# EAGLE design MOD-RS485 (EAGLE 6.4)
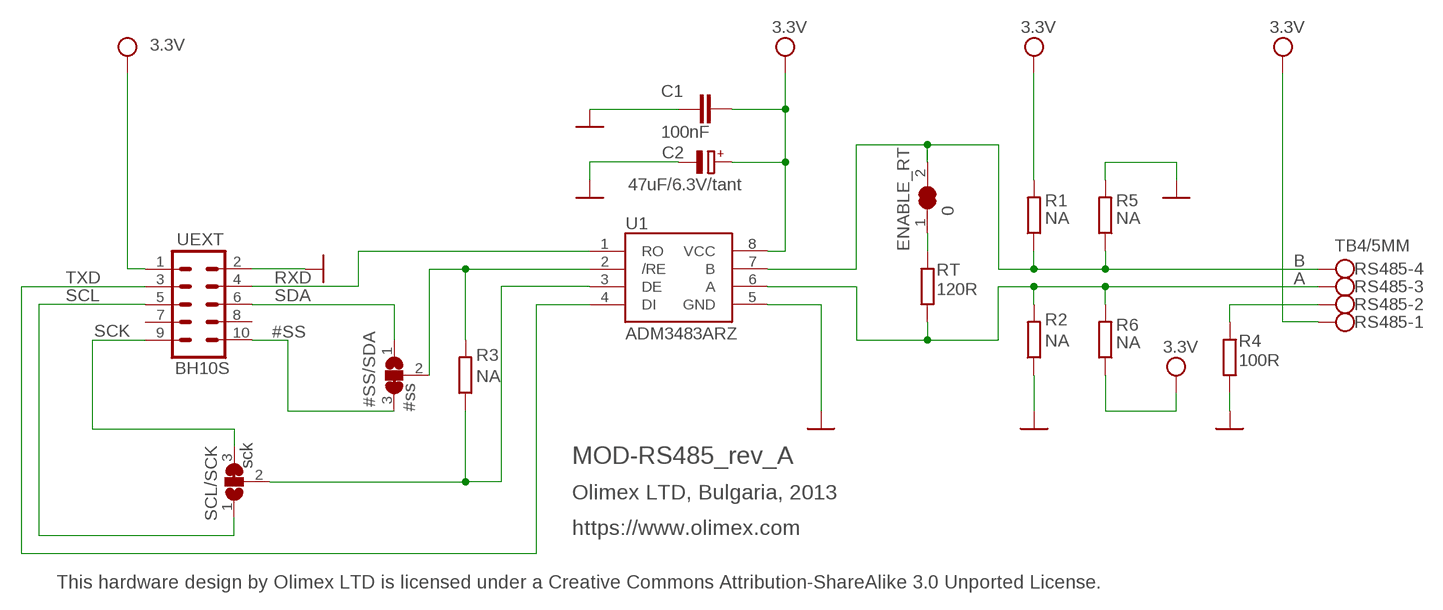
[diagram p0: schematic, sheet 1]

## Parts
#SS/SDA  SJ2W  [SJ_2]
C1  100nF  C-EUC0603_5MIL  [C0603_5MIL]
C2  47uF/6.3V/tant  CPOL-EUCT3528  [CT3528]
ENABLE_RT  0  SJ  [SJ]
R1  NA  R-EU_R0603_5MIL  [R0603_5MIL]
R2  NA  R-EU_R0603_5MIL  [R0603_5MIL]
R3  NA  R-EU_R0603_5MIL  [R0603_5MIL]
R4  100R  R-EU_R1206_5MIL  [R1206_5MIL]
R5  NA  R-EU_R0603_5MIL  [R0603_5MIL]
R6  NA  R-EU_R0603_5MIL  [R0603_5MIL]
RS485  TB4/5MM  W237-4  [W237-4]
RT  120R  R-EU_R1206_5MIL  [R1206_5MIL]
SCL/SCK  sck  SJ2W  [SJ_2]
U1  ADM3483ARZ  ADM3483  [SOIC8]
UEXT  BH10S  AVRICSP2  [CON2X5_SS2]

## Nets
#SS: #SS/SDA.3 UEXT.10
A: R2.2 R6.2 RS485.3 RT.1 U1.6(A)
B: ENABLE_RT.2 R1.1 R5.1 RS485.4 U1.7(B)
GND [pwr]: C1.1 C2.- R2.1 R4.1 R5.2 U1.5(GND) UEXT.2
N$1: ENABLE_RT.1 RT.2
N$2: #SS/SDA.2 R3.2 U1.2(/RE)
N$3: R4.2 RS485.2
N$4: R3.1 SCL/SCK.2 U1.3(DE)
RXD: U1.1(RO) UEXT.4
SCK: SCL/SCK.3 UEXT.9
SCL: SCL/SCK.1 UEXT.5
SDA: #SS/SDA.1 UEXT.6
TXD: U1.4(DI) UEXT.3
VCC: C1.2 C2.+ R1.2 R6.1 RS485.1 U1.8(VCC) UEXT.1 ; supply symbol labelled 3.3V
Unconnected: UEXT.7 UEXT.8

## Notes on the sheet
- #ss
- MOD-RS485_rev_A
- Olimex LTD, Bulgaria, 2013
- https://www.olimex.com
- This hardware design by Olimex LTD is licensed under a Creative Commons Attribution-ShareAlike 3.0 Unported License.

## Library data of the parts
#SS/SDA SCL/SCK = jumper:SJ2W: SMD solder JUMPER
C1 = rcl:C-EU: CAPACITOR, European symbol
C2 = rcl:CPOL-EU: POLARIZED CAPACITOR, European symbol
ENABLE_RT = jumper:SJ: SMD solder JUMPER
R1-R6 RT = rcl:R-EU_: RESISTOR, European symbol
RS485 = con-wago-500:W237-4: WAGO SCREW CLAMP
U1 = OLIMEX_IC:ADM3483: ADUM3483(SOIC8) RS-485 half duplex transciever
UEXT = gogo:AVRICSP

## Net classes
1 pwr: width 0.4 mm, clearance 0.23 mm

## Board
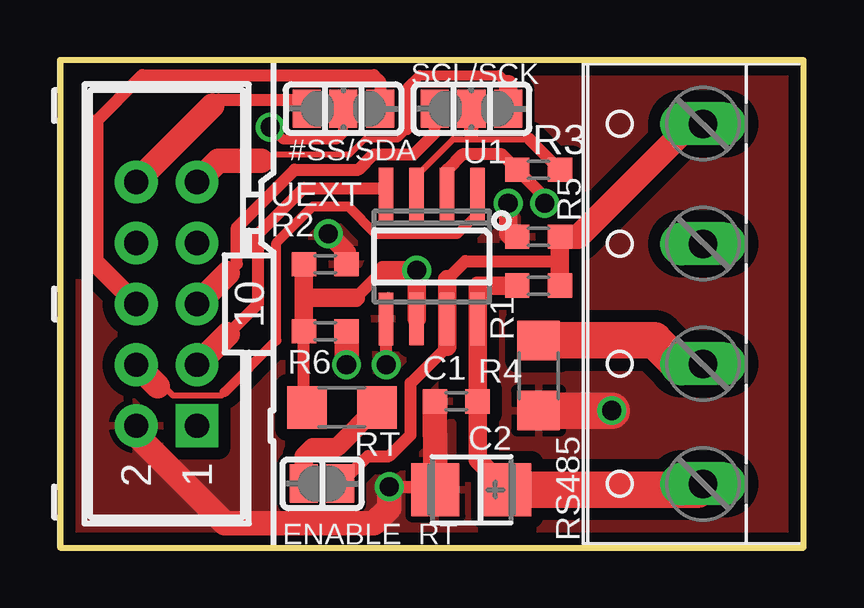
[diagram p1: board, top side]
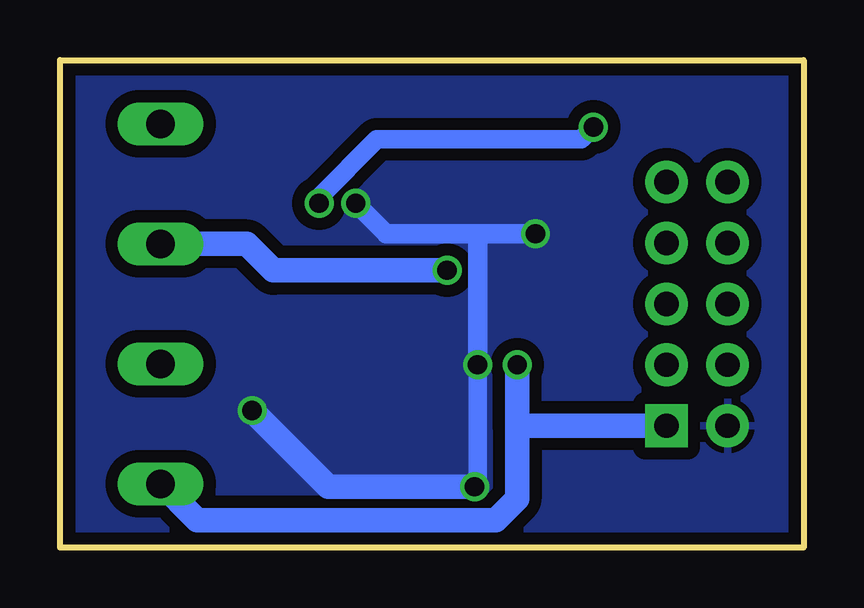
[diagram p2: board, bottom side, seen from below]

Size 30.99 x 20.32 mm. Coordinates in mm from the lower left corner, seen from the top.
Outline: 0,0 30.99,0 30.99,20.32 0,20.32 0,0
Copper layers (1*16): Top 0.035mm / dielectric 1.5mm / Bottom 0.035mm
Design rules "default": minimum track width 12mil, minimum drill 24mil, track to track 10mil, track to pad 10mil, pad to pad 10mil, via to via 10mil, smd to smd 8mil, copper to edge 10mil, drill to drill 8mil, minimum pad ring 10mil, minimum via ring 8mil, stop-mask expansion 4mil, vias tented up to drill 32mil, thermal gap 10mil

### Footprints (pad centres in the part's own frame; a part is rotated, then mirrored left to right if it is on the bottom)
SJ_2 = smd 1.168 x 1.6: 1 -1.524,0; 2 0,0; 3 1.524,0
C0603_5MIL = smd 1.016 x 1.016: 1 -0.889,0; 2 0.889,0
CT3528 = smd 2 x 2.2: + -1.5,0; - 1.5,0
SJ = smd 1.168 x 1.6: 1 -0.762,0; 2 0.762,0
R0603_5MIL = smd 1.016 x 1.016: 1 -0.889,0; 2 0.889,0
R1206_5MIL = smd 1.651 x 1.778: 1 -1.46,0; 2 1.46,0
W237-4 = drill 1.194 long: 1 -7.5,-1.27; 2 -2.5,-1.27; 3 2.5,-1.27; 4 7.5,-1.27
SOIC8 = smd 0.6 x 2.2: 1 -1.905,-2.6; 2 -0.635,-2.6; 3 0.635,-2.6; 4 1.905,-2.6; 5 1.905,2.6; 6 0.635,2.6; 7 -0.635,2.6; 8 -1.905,2.6
CON2X5_SS2 = drill 1.016 pad 1.778 square: 1 -5.08,-1.27 | drill 1.016 pad 1.778 round: 2 -5.08,1.27; 3 -2.54,-1.27; 4 -2.54,1.27; 5 0,-1.27; 6 0,1.27; 7 2.54,-1.27; 8 2.54,1.27; 9 5.08,-1.27; 10 5.08,1.27

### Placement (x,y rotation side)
#SS/SDA  11.81,18.29 180 top
C1  16.51,6.1 0 top
C2  17.14,2.41 180 top
ENABLE_RT  10.92,2.67 0 top
R1  19.94,10.92 180 top
R2  11.05,11.81 180 top
R3  19.94,15.75 180 top
R4  19.94,7.18 90 top
R5  19.94,12.95 180 top
R6  11.05,9.02 180 top
RS485  25.53,10.16 90 top
RT  11.75,5.84 0 top
SCL/SCK  17.14,18.29 0 top
U1  15.49,12.13 180 top
U$2  [ESD_STOP]  20.19,2.41 0 bottom
U$3  [PB_SMAL_STOP]  9.02,8.51 0 bottom
U$4  [RECYCLE_BIN1/8_TOPSTOP]  24.51,4.19 0 bottom
UEXT  4.45,10.16 90 top

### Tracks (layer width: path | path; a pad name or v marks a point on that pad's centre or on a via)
#SS
  Top 0.508: 6.35,18.41 6.6,18.67 10.29,18.67 #SS/SDA.3
  Top 1.016: UEXT.10 6.35,18.41
A  (via drill 0.8)
  Top 0.508: RT.1 10.16,5.97 R6.2 | 12.32,10.41 13.46,11.56
  Top 0.762: R6.2 10.16,10.41 | 10.16,10.41 R2.2 | U1.6 v14.86,11.56 13.46,11.56 | 10.16,10.41 12.32,10.41
  Bottom 1.016: RS485.3 23.2,12.66 22.1,11.56 v14.86,11.56
B
  Top 0.508: 16.13,11.18 16.89,11.94 20.83,11.94 | 16.13,8.38 14.61,6.86 14.61,4.7 13.72,3.81 12.83,3.81 ENABLE_RT.2
  Top 0.762: R1.1 20.83,11.94 R5.1 | 16.13,8.38 U1.7 16.13,11.18
  Top 1.016: RS485.4 26.3,17.66 21.59,12.95 R5.1
GND  (via drill 0.8)
  Top 0.508: v13.72,2.54 15.64,2.54 C2.- | v13.59,7.62 U1.5
  Top 0.762: v18.67,14.35 18.67,13.08 18.8,12.95 R5.2 | v11.18,13.08 11.94,12.32 R2.1
  Top 1.016: C2.- 15.64,4.67 15.62,4.7 C1.1 | v13.72,2.54 13.72,1.65 13.08,1.02 6.86,1.02 3.17,4.7 UEXT.2
  Top 1.524: v22.99,5.71 R4.1
  Bottom 0.762: v13.59,7.62 13.59,2.67 v13.72,2.54
  Bottom 0.813: 13.59,13.08 17.4,13.08 v18.67,14.35 | 13.59,13.08 v11.18,13.08 | v13.59,7.62 13.59,13.08
  Bottom 1.016: v13.72,2.54 19.81,2.54 v22.99,5.71
  pour Top (isolate 0.508): -0.38,21.08 33.27,21.08 33.27,-1.14 -0.38,-1.14
  pour Bottom (isolate 0.508): -1.65,22.99 34.54,22.99 34.54,-2.54 -1.65,-2.54
N$1
  Top 0.762: RT.2 11.56,4.19 10.54,4.19 10.16,3.81 ENABLE_RT.1
N$2  (via drill 0.8)
  Top 0.406: #SS/SDA.2 11.81,17.27 11.56,17.02 9.27,17.02 v8.76,17.53
  Top 0.508: U1.2 16.13,15.75 16.76,16.38 18.41,16.38 R3.2 20.19,14.61 v20.19,14.35
  Bottom 0.762: v8.76,17.53 9.27,17.02 17.78,17.02 20.19,14.61 v20.19,14.35
N$3
  Top 1.524: RS485.2 25.74,7.66 24.77,8.64 R4.2
N$4
  Top 0.254: 17.14,17.02 19.56,17.02 | U1.3 14.86,15.49 16.38,17.02 17.14,17.02 | 17.14,17.02 17.14,17.27
  Top 0.508: 19.56,17.02 R3.1
  Top 0.61: 17.14,17.27 SCL/SCK.2
RXD
  Top 0.254: 4.06,6.73 4.32,6.73 4.7,6.35 6.73,6.35 6.86,6.48
  Top 0.406: 6.86,6.48 9.02,8.64 9.02,12.7 10.54,14.22 12,14.22 13.14,13.08 16.57,13.08 17.4,13.91 U1.1
  Top 1.016: 4.06,6.73 UEXT.4
SCK
  Top 0.254: 8.38,16.13 8.64,16.13 8.89,16.38 12.06,16.38 12.7,17.02 14.1,17.02 14.48,17.4
  Top 0.406: 14.48,17.4 14.48,19.18 14.99,19.68 18.29,19.68 18.67,19.3
  Top 0.762: 18.67,19.3 SCL/SCK.3
  Top 1.016: UEXT.9 6.6,16.13 8.38,16.13
SCL
  Top 0.508: 6.99,11.43 7.37,11.81 7.37,13.34 9.78,15.75 12.45,15.75 13.08,16.38 14.73,16.38 15.62,17.27 SCL/SCK.1
  Top 1.016: UEXT.5 6.99,11.43
SDA
  Top 0.508: 1.4,17.65 3.43,19.68 13.08,19.68 13.34,19.43 #SS/SDA.1
  Top 0.813: UEXT.6 1.4,11.94 1.4,17.65
TXD
  Top 0.508: U1.4 13.59,14.99 10.16,14.99 8.26,13.08 8.26,10.16 6.99,8.89
  Top 1.016: UEXT.3 6.99,8.89
VCC  (via drill 0.8)
  Top 0.762: R1.2 17.4,10.92 U1.8 C1.2 17.4,3.66 C2.+
  Top 1.016: v11.94,7.62 R6.1 | RS485.1 26.55,2.41
  Top 1.524: 26.55,2.41 C2.+
  Bottom 1.016: 11.94,5.08 v11.94,7.62 | UEXT.1 11.94,5.08 | 11.94,5.08 11.94,2.03 12.83,1.14 25.27,1.14 26.03,1.9 26.03,1.91 RS485.1

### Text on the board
bStop: WWW.OLIMEX.COM/DEV | B | RoHS Compliant | A | GND | 3.3V | COPYRIGHT(C) 2010 | MOD-RS485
